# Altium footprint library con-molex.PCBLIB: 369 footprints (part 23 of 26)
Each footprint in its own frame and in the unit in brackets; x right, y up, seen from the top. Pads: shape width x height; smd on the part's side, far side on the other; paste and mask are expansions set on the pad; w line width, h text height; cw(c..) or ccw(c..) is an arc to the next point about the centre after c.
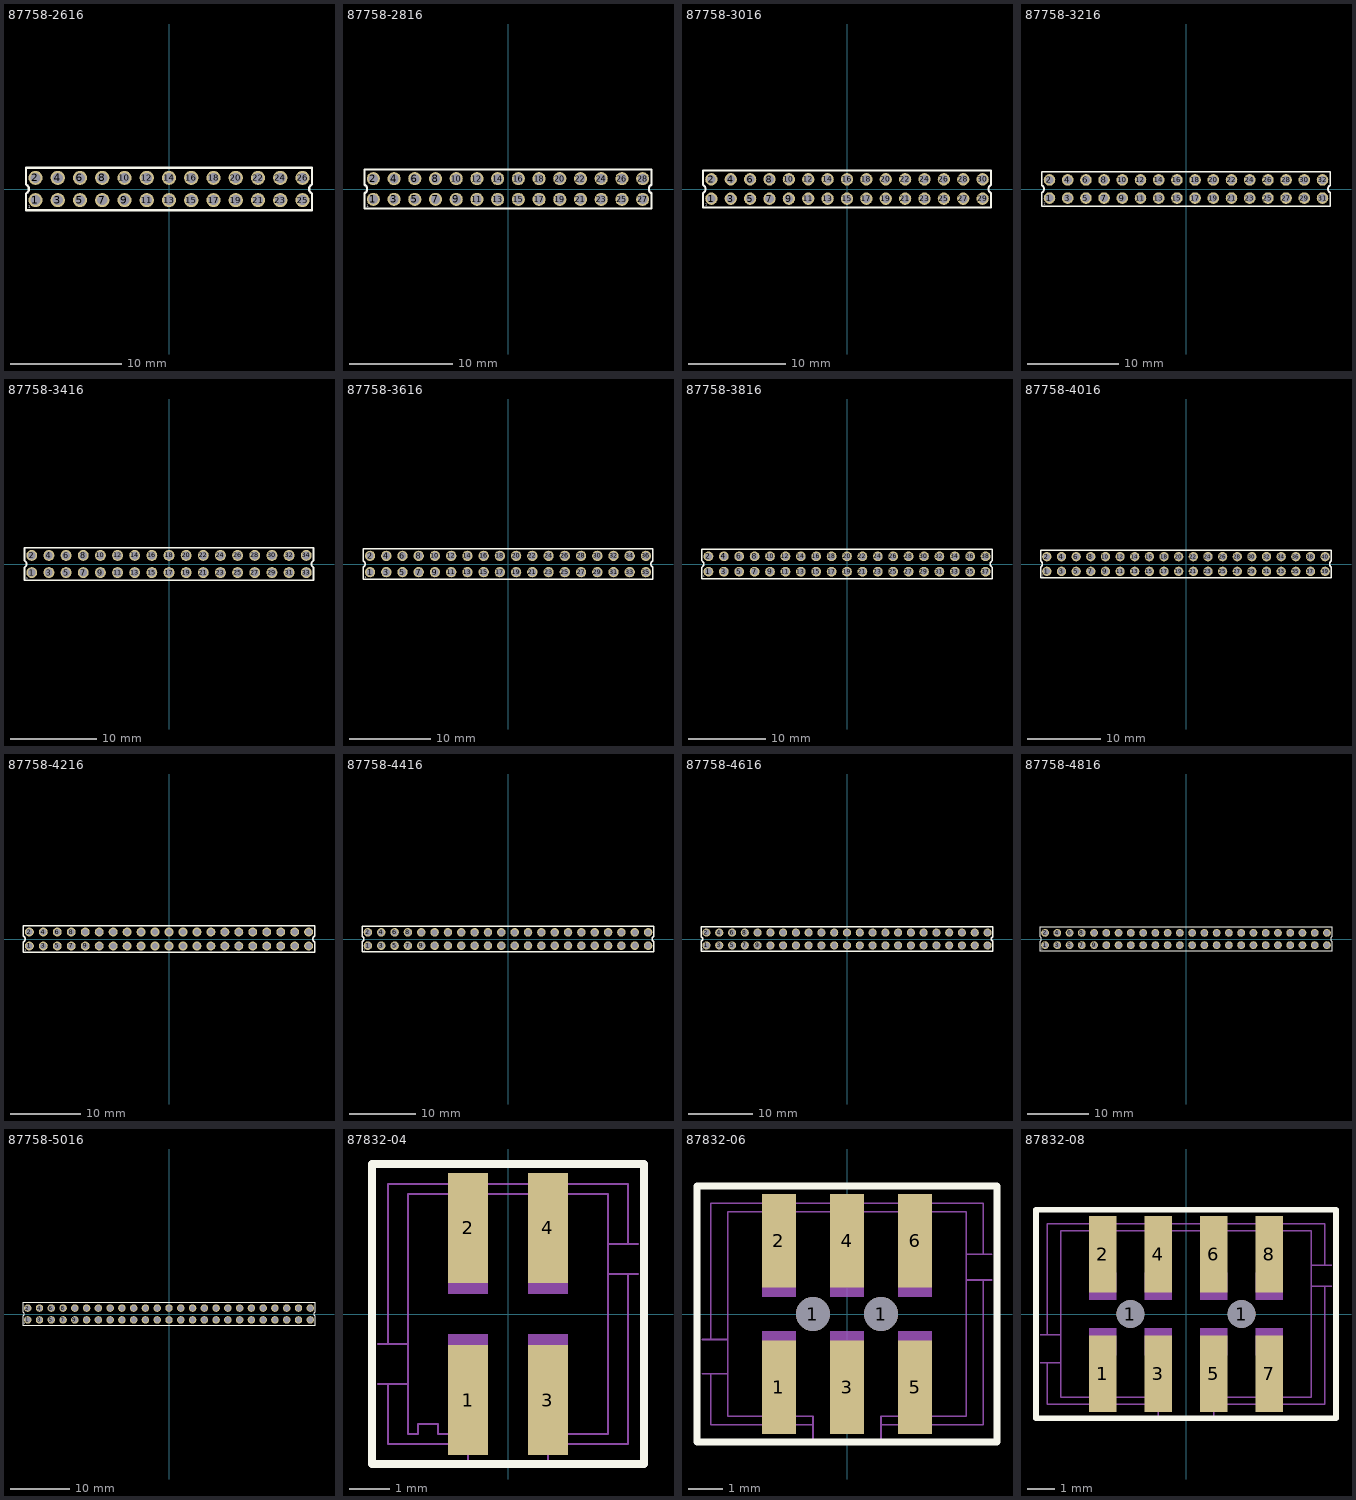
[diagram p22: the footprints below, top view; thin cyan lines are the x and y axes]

## 87758-2616 [mm]
pads (26):
  round 1.27 hole 0.9: 1(-12,-1) 2(-12,1) 3(-10,-1) 4(-10,1) 5(-8,-1) 6(-8,1) 7(-6,-1) 8(-6,1) 9(-4,-1) 10(-4,1) 11(-2,-1) 12(-2,1) 13(0,-1) 14(0,1) 15(2,-1) 16(2,1) 17(4,-1) 18(4,1) 19(6,-1) 20(6,1) 21(8,-1) 22(8,1) 23(10,-1) 24(10,1) 25(12,-1) 26(12,1)
Top Overlay:
  lines w0.203: -12.85,-1.9 12.85,-1.9 12.85,-0.4 cw(c13.04,0) 12.85,0.4 12.85,1.9 -12.85,1.9 -12.85,0.4 cw(c-13.04,0) -12.85,-0.4 -12.85,-1.9
  text "1" at -12.65,-1.75 h0.26
Mechanical 16:
  rectangle: -12.25,-1.25 -11.75,-0.75
  rectangle: -12.25,0.75 -11.75,1.25
  rectangle: -10.25,-1.25 -9.75,-0.75
  rectangle: -10.25,0.75 -9.75,1.25
  rectangle: -8.25,-1.25 -7.75,-0.75
  rectangle: -8.25,0.75 -7.75,1.25
  rectangle: -6.25,-1.25 -5.75,-0.75
  rectangle: -6.25,0.75 -5.75,1.25
  rectangle: -4.25,-1.25 -3.75,-0.75
  rectangle: -4.25,0.75 -3.75,1.25
  rectangle: -2.25,-1.25 -1.75,-0.75
  rectangle: -2.25,0.75 -1.75,1.25
  rectangle: -0.25,-1.25 0.25,-0.75
  rectangle: -0.25,0.75 0.25,1.25
  rectangle: 1.75,-1.25 2.25,-0.75
  rectangle: 1.75,0.75 2.25,1.25
  rectangle: 3.75,-1.25 4.25,-0.75
  rectangle: 3.75,0.75 4.25,1.25
  rectangle: 5.75,-1.25 6.25,-0.75
  rectangle: 5.75,0.75 6.25,1.25
  rectangle: 7.75,-1.25 8.25,-0.75
  rectangle: 7.75,0.75 8.25,1.25
  rectangle: 9.75,-1.25 10.25,-0.75
  rectangle: 9.75,0.75 10.25,1.25
  rectangle: 11.75,-1.25 12.25,-0.75
  rectangle: 11.75,0.75 12.25,1.25

## 87758-2816 [mm]
pads (28):
  round 1.27 hole 0.9: 1(-13,-1) 2(-13,1) 3(-11,-1) 4(-11,1) 5(-9,-1) 6(-9,1) 7(-7,-1) 8(-7,1) 9(-5,-1) 10(-5,1) 11(-3,-1) 12(-3,1) 13(-1,-1) 14(-1,1) 15(1,-1) 16(1,1) 17(3,-1) 18(3,1) 19(5,-1) 20(5,1) 21(7,-1) 22(7,1) 23(9,-1) 24(9,1) 25(11,-1) 26(11,1) 27(13,-1) 28(13,1)
Top Overlay:
  lines w0.203: -13.85,-1.9 13.85,-1.9 13.85,-0.4 cw(c14.04,0) 13.85,0.4 13.85,1.9 -13.85,1.9 -13.85,0.4 cw(c-14.04,0) -13.85,-0.4 -13.85,-1.9
  text "1" at -13.65,-1.75 h0.26
Mechanical 16:
  rectangle: -13.25,-1.25 -12.75,-0.75
  rectangle: -13.25,0.75 -12.75,1.25
  rectangle: -11.25,-1.25 -10.75,-0.75
  rectangle: -11.25,0.75 -10.75,1.25
  rectangle: -9.25,-1.25 -8.75,-0.75
  rectangle: -9.25,0.75 -8.75,1.25
  rectangle: -7.25,-1.25 -6.75,-0.75
  rectangle: -7.25,0.75 -6.75,1.25
  rectangle: -5.25,-1.25 -4.75,-0.75
  rectangle: -5.25,0.75 -4.75,1.25
  rectangle: -3.25,-1.25 -2.75,-0.75
  rectangle: -3.25,0.75 -2.75,1.25
  rectangle: -1.25,-1.25 -0.75,-0.75
  rectangle: -1.25,0.75 -0.75,1.25
  rectangle: 0.75,-1.25 1.25,-0.75
  rectangle: 0.75,0.75 1.25,1.25
  rectangle: 2.75,-1.25 3.25,-0.75
  rectangle: 2.75,0.75 3.25,1.25
  rectangle: 4.75,-1.25 5.25,-0.75
  rectangle: 4.75,0.75 5.25,1.25
  rectangle: 6.75,-1.25 7.25,-0.75
  rectangle: 6.75,0.75 7.25,1.25
  rectangle: 8.75,-1.25 9.25,-0.75
  rectangle: 8.75,0.75 9.25,1.25
  rectangle: 10.75,-1.25 11.25,-0.75
  rectangle: 10.75,0.75 11.25,1.25
  rectangle: 12.75,-1.25 13.25,-0.75
  rectangle: 12.75,0.75 13.25,1.25

## 87758-3016 [mm]
pads (30):
  round 1.27 hole 0.9: 1(-14,-1) 2(-14,1) 3(-12,-1) 4(-12,1) 5(-10,-1) 6(-10,1) 7(-8,-1) 8(-8,1) 9(-6,-1) 10(-6,1) 11(-4,-1) 12(-4,1) 13(-2,-1) 14(-2,1) 15(0,-1) 16(0,1) 17(2,-1) 18(2,1) 19(4,-1) 20(4,1) 21(6,-1) 22(6,1) 23(8,-1) 24(8,1) 25(10,-1) 26(10,1) 27(12,-1) 28(12,1) 29(14,-1) 30(14,1)
Top Overlay:
  lines w0.203: -14.85,-1.9 14.85,-1.9 14.85,-0.4 cw(c15.04,0) 14.85,0.4 14.85,1.9 -14.85,1.9 -14.85,0.4 cw(c-15.04,0) -14.85,-0.4 -14.85,-1.9
  text "1" at -14.65,-1.75 h0.26
Mechanical 16:
  rectangle: -14.25,-1.25 -13.75,-0.75
  rectangle: -14.25,0.75 -13.75,1.25
  rectangle: -12.25,-1.25 -11.75,-0.75
  rectangle: -12.25,0.75 -11.75,1.25
  rectangle: -10.25,-1.25 -9.75,-0.75
  rectangle: -10.25,0.75 -9.75,1.25
  rectangle: -8.25,-1.25 -7.75,-0.75
  rectangle: -8.25,0.75 -7.75,1.25
  rectangle: -6.25,-1.25 -5.75,-0.75
  rectangle: -6.25,0.75 -5.75,1.25
  rectangle: -4.25,-1.25 -3.75,-0.75
  rectangle: -4.25,0.75 -3.75,1.25
  rectangle: -2.25,-1.25 -1.75,-0.75
  rectangle: -2.25,0.75 -1.75,1.25
  rectangle: -0.25,-1.25 0.25,-0.75
  rectangle: -0.25,0.75 0.25,1.25
  rectangle: 1.75,-1.25 2.25,-0.75
  rectangle: 1.75,0.75 2.25,1.25
  rectangle: 3.75,-1.25 4.25,-0.75
  rectangle: 3.75,0.75 4.25,1.25
  rectangle: 5.75,-1.25 6.25,-0.75
  rectangle: 5.75,0.75 6.25,1.25
  rectangle: 7.75,-1.25 8.25,-0.75
  rectangle: 7.75,0.75 8.25,1.25
  rectangle: 9.75,-1.25 10.25,-0.75
  rectangle: 9.75,0.75 10.25,1.25
  rectangle: 11.75,-1.25 12.25,-0.75
  rectangle: 11.75,0.75 12.25,1.25
  rectangle: 13.75,-1.25 14.25,-0.75
  rectangle: 13.75,0.75 14.25,1.25

## 87758-3216 [mm]
pads (32):
  round 1.27 hole 0.9: 1(-15,-1) 2(-15,1) 3(-13,-1) 4(-13,1) 5(-11,-1) 6(-11,1) 7(-9,-1) 8(-9,1) 9(-7,-1) 10(-7,1) 11(-5,-1) 12(-5,1) 13(-3,-1) 14(-3,1) 15(-1,-1) 16(-1,1) 17(1,-1) 18(1,1) 19(3,-1) 20(3,1) 21(5,-1) 22(5,1) 23(7,-1) 24(7,1) 25(9,-1) 26(9,1) 27(11,-1) 28(11,1) 29(13,-1) 30(13,1) 31(15,-1) 32(15,1)
Top Overlay:
  lines w0.203: -15.85,-1.9 15.85,-1.9 15.85,-0.4 cw(c16.04,0) 15.85,0.4 15.85,1.9 -15.85,1.9 -15.85,0.4 cw(c-16.04,0) -15.85,-0.4 -15.85,-1.9
  text "1" at -15.65,-1.75 h0.26
Mechanical 16:
  rectangle: -15.25,-1.25 -14.75,-0.75
  rectangle: -15.25,0.75 -14.75,1.25
  rectangle: -13.25,-1.25 -12.75,-0.75
  rectangle: -13.25,0.75 -12.75,1.25
  rectangle: -11.25,-1.25 -10.75,-0.75
  rectangle: -11.25,0.75 -10.75,1.25
  rectangle: -9.25,-1.25 -8.75,-0.75
  rectangle: -9.25,0.75 -8.75,1.25
  rectangle: -7.25,-1.25 -6.75,-0.75
  rectangle: -7.25,0.75 -6.75,1.25
  rectangle: -5.25,-1.25 -4.75,-0.75
  rectangle: -5.25,0.75 -4.75,1.25
  rectangle: -3.25,-1.25 -2.75,-0.75
  rectangle: -3.25,0.75 -2.75,1.25
  rectangle: -1.25,-1.25 -0.75,-0.75
  rectangle: -1.25,0.75 -0.75,1.25
  rectangle: 0.75,-1.25 1.25,-0.75
  rectangle: 0.75,0.75 1.25,1.25
  rectangle: 2.75,-1.25 3.25,-0.75
  rectangle: 2.75,0.75 3.25,1.25
  rectangle: 4.75,-1.25 5.25,-0.75
  rectangle: 4.75,0.75 5.25,1.25
  rectangle: 6.75,-1.25 7.25,-0.75
  rectangle: 6.75,0.75 7.25,1.25
  rectangle: 8.75,-1.25 9.25,-0.75
  rectangle: 8.75,0.75 9.25,1.25
  rectangle: 10.75,-1.25 11.25,-0.75
  rectangle: 10.75,0.75 11.25,1.25
  rectangle: 12.75,-1.25 13.25,-0.75
  rectangle: 12.75,0.75 13.25,1.25
  rectangle: 14.75,-1.25 15.25,-0.75
  rectangle: 14.75,0.75 15.25,1.25

## 87758-3416 [mm]
pads (34):
  round 1.27 hole 0.9: 1(-16,-1) 2(-16,1) 3(-14,-1) 4(-14,1) 5(-12,-1) 6(-12,1) 7(-10,-1) 8(-10,1) 9(-8,-1) 10(-8,1) 11(-6,-1) 12(-6,1) 13(-4,-1) 14(-4,1) 15(-2,-1) 16(-2,1) 17(0,-1) 18(0,1) 19(2,-1) 20(2,1) 21(4,-1) 22(4,1) 23(6,-1) 24(6,1) 25(8,-1) 26(8,1) 27(10,-1) 28(10,1) 29(12,-1) 30(12,1) 31(14,-1) 32(14,1) 33(16,-1) 34(16,1)
Top Overlay:
  lines w0.203: -16.85,-1.9 16.85,-1.9 16.85,-0.4 cw(c17.04,0) 16.85,0.4 16.85,1.9 -16.85,1.9 -16.85,0.4 cw(c-17.04,0) -16.85,-0.4 -16.85,-1.9
  text "1" at -16.65,-1.75 h0.26
Mechanical 16:
  rectangle: -16.25,-1.25 -15.75,-0.75
  rectangle: -16.25,0.75 -15.75,1.25
  rectangle: -14.25,-1.25 -13.75,-0.75
  rectangle: -14.25,0.75 -13.75,1.25
  rectangle: -12.25,-1.25 -11.75,-0.75
  rectangle: -12.25,0.75 -11.75,1.25
  rectangle: -10.25,-1.25 -9.75,-0.75
  rectangle: -10.25,0.75 -9.75,1.25
  rectangle: -8.25,-1.25 -7.75,-0.75
  rectangle: -8.25,0.75 -7.75,1.25
  rectangle: -6.25,-1.25 -5.75,-0.75
  rectangle: -6.25,0.75 -5.75,1.25
  rectangle: -4.25,-1.25 -3.75,-0.75
  rectangle: -4.25,0.75 -3.75,1.25
  rectangle: -2.25,-1.25 -1.75,-0.75
  rectangle: -2.25,0.75 -1.75,1.25
  rectangle: -0.25,-1.25 0.25,-0.75
  rectangle: -0.25,0.75 0.25,1.25
  rectangle: 1.75,-1.25 2.25,-0.75
  rectangle: 1.75,0.75 2.25,1.25
  rectangle: 3.75,-1.25 4.25,-0.75
  rectangle: 3.75,0.75 4.25,1.25
  rectangle: 5.75,-1.25 6.25,-0.75
  rectangle: 5.75,0.75 6.25,1.25
  rectangle: 7.75,-1.25 8.25,-0.75
  rectangle: 7.75,0.75 8.25,1.25
  rectangle: 9.75,-1.25 10.25,-0.75
  rectangle: 9.75,0.75 10.25,1.25
  rectangle: 11.75,-1.25 12.25,-0.75
  rectangle: 11.75,0.75 12.25,1.25
  rectangle: 13.75,-1.25 14.25,-0.75
  rectangle: 13.75,0.75 14.25,1.25
  rectangle: 15.75,-1.25 16.25,-0.75
  rectangle: 15.75,0.75 16.25,1.25

## 87758-3616 [mm]
pads (36):
  round 1.27 hole 0.9: 1(-17,-1) 2(-17,1) 3(-15,-1) 4(-15,1) 5(-13,-1) 6(-13,1) 7(-11,-1) 8(-11,1) 9(-9,-1) 10(-9,1) 11(-7,-1) 12(-7,1) 13(-5,-1) 14(-5,1) 15(-3,-1) 16(-3,1) 17(-1,-1) 18(-1,1) 19(1,-1) 20(1,1) 21(3,-1) 22(3,1) 23(5,-1) 24(5,1) 25(7,-1) 26(7,1) 27(9,-1) 28(9,1) 29(11,-1) 30(11,1) 31(13,-1) 32(13,1) 33(15,-1) 34(15,1) 35(17,-1) 36(17,1)
Top Overlay:
  lines w0.203: -17.85,-1.9 17.85,-1.9 17.85,-0.4 cw(c18.04,0) 17.85,0.4 17.85,1.9 -17.85,1.9 -17.85,0.4 cw(c-18.04,0) -17.85,-0.4 -17.85,-1.9
  text "1" at -17.65,-1.75 h0.26
Mechanical 16:
  rectangle: -17.25,-1.25 -16.75,-0.75
  rectangle: -17.25,0.75 -16.75,1.25
  rectangle: -15.25,-1.25 -14.75,-0.75
  rectangle: -15.25,0.75 -14.75,1.25
  rectangle: -13.25,-1.25 -12.75,-0.75
  rectangle: -13.25,0.75 -12.75,1.25
  rectangle: -11.25,-1.25 -10.75,-0.75
  rectangle: -11.25,0.75 -10.75,1.25
  rectangle: -9.25,-1.25 -8.75,-0.75
  rectangle: -9.25,0.75 -8.75,1.25
  rectangle: -7.25,-1.25 -6.75,-0.75
  rectangle: -7.25,0.75 -6.75,1.25
  rectangle: -5.25,-1.25 -4.75,-0.75
  rectangle: -5.25,0.75 -4.75,1.25
  rectangle: -3.25,-1.25 -2.75,-0.75
  rectangle: -3.25,0.75 -2.75,1.25
  rectangle: -1.25,-1.25 -0.75,-0.75
  rectangle: -1.25,0.75 -0.75,1.25
  rectangle: 0.75,-1.25 1.25,-0.75
  rectangle: 0.75,0.75 1.25,1.25
  rectangle: 2.75,-1.25 3.25,-0.75
  rectangle: 2.75,0.75 3.25,1.25
  rectangle: 4.75,-1.25 5.25,-0.75
  rectangle: 4.75,0.75 5.25,1.25
  rectangle: 6.75,-1.25 7.25,-0.75
  rectangle: 6.75,0.75 7.25,1.25
  rectangle: 8.75,-1.25 9.25,-0.75
  rectangle: 8.75,0.75 9.25,1.25
  rectangle: 10.75,-1.25 11.25,-0.75
  rectangle: 10.75,0.75 11.25,1.25
  rectangle: 12.75,-1.25 13.25,-0.75
  rectangle: 12.75,0.75 13.25,1.25
  rectangle: 14.75,-1.25 15.25,-0.75
  rectangle: 14.75,0.75 15.25,1.25
  rectangle: 16.75,-1.25 17.25,-0.75
  rectangle: 16.75,0.75 17.25,1.25

## 87758-3816 [mm]
pads (38):
  round 1.27 hole 0.9: 1(-18,-1) 2(-18,1) 3(-16,-1) 4(-16,1) 5(-14,-1) 6(-14,1) 7(-12,-1) 8(-12,1) 9(-10,-1) 10(-10,1) 11(-8,-1) 12(-8,1) 13(-6,-1) 14(-6,1) 15(-4,-1) 16(-4,1) 17(-2,-1) 18(-2,1) 19(0,-1) 20(0,1) 21(2,-1) 22(2,1) 23(4,-1) 24(4,1) 25(6,-1) 26(6,1) 27(8,-1) 28(8,1) 29(10,-1) 30(10,1) 31(12,-1) 32(12,1) 33(14,-1) 34(14,1) 35(16,-1) 36(16,1) 37(18,-1) 38(18,1)
Top Overlay:
  lines w0.203: -18.85,-1.9 18.85,-1.9 18.85,-0.4 cw(c19.04,0) 18.85,0.4 18.85,1.9 -18.85,1.9 -18.85,0.4 cw(c-19.04,0) -18.85,-0.4 -18.85,-1.9
  text "1" at -18.65,-1.75 h0.26
Mechanical 16:
  rectangle: -18.25,-1.25 -17.75,-0.75
  rectangle: -18.25,0.75 -17.75,1.25
  rectangle: -16.25,-1.25 -15.75,-0.75
  rectangle: -16.25,0.75 -15.75,1.25
  rectangle: -14.25,-1.25 -13.75,-0.75
  rectangle: -14.25,0.75 -13.75,1.25
  rectangle: -12.25,-1.25 -11.75,-0.75
  rectangle: -12.25,0.75 -11.75,1.25
  rectangle: -10.25,-1.25 -9.75,-0.75
  rectangle: -10.25,0.75 -9.75,1.25
  rectangle: -8.25,-1.25 -7.75,-0.75
  rectangle: -8.25,0.75 -7.75,1.25
  rectangle: -6.25,-1.25 -5.75,-0.75
  rectangle: -6.25,0.75 -5.75,1.25
  rectangle: -4.25,-1.25 -3.75,-0.75
  rectangle: -4.25,0.75 -3.75,1.25
  rectangle: -2.25,-1.25 -1.75,-0.75
  rectangle: -2.25,0.75 -1.75,1.25
  rectangle: -0.25,-1.25 0.25,-0.75
  rectangle: -0.25,0.75 0.25,1.25
  rectangle: 1.75,-1.25 2.25,-0.75
  rectangle: 1.75,0.75 2.25,1.25
  rectangle: 3.75,-1.25 4.25,-0.75
  rectangle: 3.75,0.75 4.25,1.25
  rectangle: 5.75,-1.25 6.25,-0.75
  rectangle: 5.75,0.75 6.25,1.25
  rectangle: 7.75,-1.25 8.25,-0.75
  rectangle: 7.75,0.75 8.25,1.25
  rectangle: 9.75,-1.25 10.25,-0.75
  rectangle: 9.75,0.75 10.25,1.25
  rectangle: 11.75,-1.25 12.25,-0.75
  rectangle: 11.75,0.75 12.25,1.25
  rectangle: 13.75,-1.25 14.25,-0.75
  rectangle: 13.75,0.75 14.25,1.25
  rectangle: 15.75,-1.25 16.25,-0.75
  rectangle: 15.75,0.75 16.25,1.25
  rectangle: 17.75,-1.25 18.25,-0.75
  rectangle: 17.75,0.75 18.25,1.25

## 87758-4016 [mm]
pads (40):
  round 1.27 hole 0.9: 1(-19,-1) 2(-19,1) 3(-17,-1) 4(-17,1) 5(-15,-1) 6(-15,1) 7(-13,-1) 8(-13,1) 9(-11,-1) 10(-11,1) 11(-9,-1) 12(-9,1) 13(-7,-1) 14(-7,1) 15(-5,-1) 16(-5,1) 17(-3,-1) 18(-3,1) 19(-1,-1) 20(-1,1) 21(1,-1) 22(1,1) 23(3,-1) 24(3,1) 25(5,-1) 26(5,1) 27(7,-1) 28(7,1) 29(9,-1) 30(9,1) 31(11,-1) 32(11,1) 33(13,-1) 34(13,1) 35(15,-1) 36(15,1) 37(17,-1) 38(17,1) 39(19,-1) 40(19,1)
Top Overlay:
  lines w0.203: -19.85,-1.9 19.85,-1.9 19.85,-0.4 cw(c20.04,0) 19.85,0.4 19.85,1.9 -19.85,1.9 -19.85,0.4 cw(c-20.04,0) -19.85,-0.4 -19.85,-1.9
  text "1" at -19.65,-1.75 h0.26
Mechanical 16:
  rectangle: -19.25,-1.25 -18.75,-0.75
  rectangle: -19.25,0.75 -18.75,1.25
  rectangle: -17.25,-1.25 -16.75,-0.75
  rectangle: -17.25,0.75 -16.75,1.25
  rectangle: -15.25,-1.25 -14.75,-0.75
  rectangle: -15.25,0.75 -14.75,1.25
  rectangle: -13.25,-1.25 -12.75,-0.75
  rectangle: -13.25,0.75 -12.75,1.25
  rectangle: -11.25,-1.25 -10.75,-0.75
  rectangle: -11.25,0.75 -10.75,1.25
  rectangle: -9.25,-1.25 -8.75,-0.75
  rectangle: -9.25,0.75 -8.75,1.25
  rectangle: -7.25,-1.25 -6.75,-0.75
  rectangle: -7.25,0.75 -6.75,1.25
  rectangle: -5.25,-1.25 -4.75,-0.75
  rectangle: -5.25,0.75 -4.75,1.25
  rectangle: -3.25,-1.25 -2.75,-0.75
  rectangle: -3.25,0.75 -2.75,1.25
  rectangle: -1.25,-1.25 -0.75,-0.75
  rectangle: -1.25,0.75 -0.75,1.25
  rectangle: 0.75,-1.25 1.25,-0.75
  rectangle: 0.75,0.75 1.25,1.25
  rectangle: 2.75,-1.25 3.25,-0.75
  rectangle: 2.75,0.75 3.25,1.25
  rectangle: 4.75,-1.25 5.25,-0.75
  rectangle: 4.75,0.75 5.25,1.25
  rectangle: 6.75,-1.25 7.25,-0.75
  rectangle: 6.75,0.75 7.25,1.25
  rectangle: 8.75,-1.25 9.25,-0.75
  rectangle: 8.75,0.75 9.25,1.25
  rectangle: 10.75,-1.25 11.25,-0.75
  rectangle: 10.75,0.75 11.25,1.25
  rectangle: 12.75,-1.25 13.25,-0.75
  rectangle: 12.75,0.75 13.25,1.25
  rectangle: 14.75,-1.25 15.25,-0.75
  rectangle: 14.75,0.75 15.25,1.25
  rectangle: 16.75,-1.25 17.25,-0.75
  rectangle: 16.75,0.75 17.25,1.25
  rectangle: 18.75,-1.25 19.25,-0.75
  rectangle: 18.75,0.75 19.25,1.25

## 87758-4216 [mm]
pads (42):
  round 1.27 hole 0.9: 1(-20,-1) 2(-20,1) 3(-18,-1) 4(-18,1) 5(-16,-1) 6(-16,1) 7(-14,-1) 8(-14,1) 9(-12,-1) 10(-12,1) 11(-10,-1) 12(-10,1) 13(-8,-1) 14(-8,1) 15(-6,-1) 16(-6,1) 17(-4,-1) 18(-4,1) 19(-2,-1) 20(-2,1) 21(0,-1) 22(0,1) 23(2,-1) 24(2,1) 25(4,-1) 26(4,1) 27(6,-1) 28(6,1) 29(8,-1) 30(8,1) 31(10,-1) 32(10,1) 33(12,-1) 34(12,1) 35(14,-1) 36(14,1) 37(16,-1) 38(16,1) 39(18,-1) 40(18,1) 41(20,-1) 42(20,1)
Top Overlay:
  lines w0.203: -20.85,-1.9 20.85,-1.9 20.85,-0.4 cw(c21.04,0) 20.85,0.4 20.85,1.9 -20.85,1.9 -20.85,0.4 cw(c-21.04,0) -20.85,-0.4 -20.85,-1.9
  text "1" at -20.65,-1.75 h0.26
Mechanical 16:
  rectangle: -20.25,-1.25 -19.75,-0.75
  rectangle: -20.25,0.75 -19.75,1.25
  rectangle: -18.25,-1.25 -17.75,-0.75
  rectangle: -18.25,0.75 -17.75,1.25
  rectangle: -16.25,-1.25 -15.75,-0.75
  rectangle: -16.25,0.75 -15.75,1.25
  rectangle: -14.25,-1.25 -13.75,-0.75
  rectangle: -14.25,0.75 -13.75,1.25
  rectangle: -12.25,-1.25 -11.75,-0.75
  rectangle: -12.25,0.75 -11.75,1.25
  rectangle: -10.25,-1.25 -9.75,-0.75
  rectangle: -10.25,0.75 -9.75,1.25
  rectangle: -8.25,-1.25 -7.75,-0.75
  rectangle: -8.25,0.75 -7.75,1.25
  rectangle: -6.25,-1.25 -5.75,-0.75
  rectangle: -6.25,0.75 -5.75,1.25
  rectangle: -4.25,-1.25 -3.75,-0.75
  rectangle: -4.25,0.75 -3.75,1.25
  rectangle: -2.25,-1.25 -1.75,-0.75
  rectangle: -2.25,0.75 -1.75,1.25
  rectangle: -0.25,-1.25 0.25,-0.75
  rectangle: -0.25,0.75 0.25,1.25
  rectangle: 1.75,-1.25 2.25,-0.75
  rectangle: 1.75,0.75 2.25,1.25
  rectangle: 3.75,-1.25 4.25,-0.75
  rectangle: 3.75,0.75 4.25,1.25
  rectangle: 5.75,-1.25 6.25,-0.75
  rectangle: 5.75,0.75 6.25,1.25
  rectangle: 7.75,-1.25 8.25,-0.75
  rectangle: 7.75,0.75 8.25,1.25
  rectangle: 9.75,-1.25 10.25,-0.75
  rectangle: 9.75,0.75 10.25,1.25
  rectangle: 11.75,-1.25 12.25,-0.75
  rectangle: 11.75,0.75 12.25,1.25
  rectangle: 13.75,-1.25 14.25,-0.75
  rectangle: 13.75,0.75 14.25,1.25
  rectangle: 15.75,-1.25 16.25,-0.75
  rectangle: 15.75,0.75 16.25,1.25
  rectangle: 17.75,-1.25 18.25,-0.75
  rectangle: 17.75,0.75 18.25,1.25
  rectangle: 19.75,-1.25 20.25,-0.75
  rectangle: 19.75,0.75 20.25,1.25

## 87758-4416 [mm]
pads (44):
  round 1.27 hole 0.9: 1(-21,-1) 2(-21,1) 3(-19,-1) 4(-19,1) 5(-17,-1) 6(-17,1) 7(-15,-1) 8(-15,1) 9(-13,-1) 10(-13,1) 11(-11,-1) 12(-11,1) 13(-9,-1) 14(-9,1) 15(-7,-1) 16(-7,1) 17(-5,-1) 18(-5,1) 19(-3,-1) 20(-3,1) 21(-1,-1) 22(-1,1) 23(1,-1) 24(1,1) 25(3,-1) 26(3,1) 27(5,-1) 28(5,1) 29(7,-1) 30(7,1) 31(9,-1) 32(9,1) 33(11,-1) 34(11,1) 35(13,-1) 36(13,1) 37(15,-1) 38(15,1) 39(17,-1) 40(17,1) 41(19,-1) 42(19,1) 43(21,-1) 44(21,1)
Top Overlay:
  lines w0.203: -21.85,-1.9 21.85,-1.9 21.85,-0.4 cw(c22.04,0) 21.85,0.4 21.85,1.9 -21.85,1.9 -21.85,0.4 cw(c-22.04,0) -21.85,-0.4 -21.85,-1.9
  text "1" at -21.65,-1.75 h0.26
Mechanical 16:
  rectangle: -21.25,-1.25 -20.75,-0.75
  rectangle: -21.25,0.75 -20.75,1.25
  rectangle: -19.25,-1.25 -18.75,-0.75
  rectangle: -19.25,0.75 -18.75,1.25
  rectangle: -17.25,-1.25 -16.75,-0.75
  rectangle: -17.25,0.75 -16.75,1.25
  rectangle: -15.25,-1.25 -14.75,-0.75
  rectangle: -15.25,0.75 -14.75,1.25
  rectangle: -13.25,-1.25 -12.75,-0.75
  rectangle: -13.25,0.75 -12.75,1.25
  rectangle: -11.25,-1.25 -10.75,-0.75
  rectangle: -11.25,0.75 -10.75,1.25
  rectangle: -9.25,-1.25 -8.75,-0.75
  rectangle: -9.25,0.75 -8.75,1.25
  rectangle: -7.25,-1.25 -6.75,-0.75
  rectangle: -7.25,0.75 -6.75,1.25
  rectangle: -5.25,-1.25 -4.75,-0.75
  rectangle: -5.25,0.75 -4.75,1.25
  rectangle: -3.25,-1.25 -2.75,-0.75
  rectangle: -3.25,0.75 -2.75,1.25
  rectangle: -1.25,-1.25 -0.75,-0.75
  rectangle: -1.25,0.75 -0.75,1.25
  rectangle: 0.75,-1.25 1.25,-0.75
  rectangle: 0.75,0.75 1.25,1.25
  rectangle: 2.75,-1.25 3.25,-0.75
  rectangle: 2.75,0.75 3.25,1.25
  rectangle: 4.75,-1.25 5.25,-0.75
  rectangle: 4.75,0.75 5.25,1.25
  rectangle: 6.75,-1.25 7.25,-0.75
  rectangle: 6.75,0.75 7.25,1.25
  rectangle: 8.75,-1.25 9.25,-0.75
  rectangle: 8.75,0.75 9.25,1.25
  rectangle: 10.75,-1.25 11.25,-0.75
  rectangle: 10.75,0.75 11.25,1.25
  rectangle: 12.75,-1.25 13.25,-0.75
  rectangle: 12.75,0.75 13.25,1.25
  rectangle: 14.75,-1.25 15.25,-0.75
  rectangle: 14.75,0.75 15.25,1.25
  rectangle: 16.75,-1.25 17.25,-0.75
  rectangle: 16.75,0.75 17.25,1.25
  rectangle: 18.75,-1.25 19.25,-0.75
  rectangle: 18.75,0.75 19.25,1.25
  rectangle: 20.75,-1.25 21.25,-0.75
  rectangle: 20.75,0.75 21.25,1.25

## 87758-4616 [mm]
pads (46):
  round 1.27 hole 0.9: 1(-22,-1) 2(-22,1) 3(-20,-1) 4(-20,1) 5(-18,-1) 6(-18,1) 7(-16,-1) 8(-16,1) 9(-14,-1) 10(-14,1) 11(-12,-1) 12(-12,1) 13(-10,-1) 14(-10,1) 15(-8,-1) 16(-8,1) 17(-6,-1) 18(-6,1) 19(-4,-1) 20(-4,1) 21(-2,-1) 22(-2,1) 23(0,-1) 24(0,1) 25(2,-1) 26(2,1) 27(4,-1) 28(4,1) 29(6,-1) 30(6,1) 31(8,-1) 32(8,1) 33(10,-1) 34(10,1) 35(12,-1) 36(12,1) 37(14,-1) 38(14,1) 39(16,-1) 40(16,1) 41(18,-1) 42(18,1) 43(20,-1) 44(20,1) 45(22,-1) 46(22,1)
Top Overlay:
  lines w0.203: -22.85,-1.9 22.85,-1.9 22.85,-0.4 cw(c23.04,0) 22.85,0.4 22.85,1.9 -22.85,1.9 -22.85,0.4 cw(c-23.04,0) -22.85,-0.4 -22.85,-1.9
  text "1" at -22.65,-1.75 h0.26
Mechanical 16:
  rectangle: -22.25,-1.25 -21.75,-0.75
  rectangle: -22.25,0.75 -21.75,1.25
  rectangle: -20.25,-1.25 -19.75,-0.75
  rectangle: -20.25,0.75 -19.75,1.25
  rectangle: -18.25,-1.25 -17.75,-0.75
  rectangle: -18.25,0.75 -17.75,1.25
  rectangle: -16.25,-1.25 -15.75,-0.75
  rectangle: -16.25,0.75 -15.75,1.25
  rectangle: -14.25,-1.25 -13.75,-0.75
  rectangle: -14.25,0.75 -13.75,1.25
  rectangle: -12.25,-1.25 -11.75,-0.75
  rectangle: -12.25,0.75 -11.75,1.25
  rectangle: -10.25,-1.25 -9.75,-0.75
  rectangle: -10.25,0.75 -9.75,1.25
  rectangle: -8.25,-1.25 -7.75,-0.75
  rectangle: -8.25,0.75 -7.75,1.25
  rectangle: -6.25,-1.25 -5.75,-0.75
  rectangle: -6.25,0.75 -5.75,1.25
  rectangle: -4.25,-1.25 -3.75,-0.75
  rectangle: -4.25,0.75 -3.75,1.25
  rectangle: -2.25,-1.25 -1.75,-0.75
  rectangle: -2.25,0.75 -1.75,1.25
  rectangle: -0.25,-1.25 0.25,-0.75
  rectangle: -0.25,0.75 0.25,1.25
  rectangle: 1.75,-1.25 2.25,-0.75
  rectangle: 1.75,0.75 2.25,1.25
  rectangle: 3.75,-1.25 4.25,-0.75
  rectangle: 3.75,0.75 4.25,1.25
  rectangle: 5.75,-1.25 6.25,-0.75
  rectangle: 5.75,0.75 6.25,1.25
  rectangle: 7.75,-1.25 8.25,-0.75
  rectangle: 7.75,0.75 8.25,1.25
  rectangle: 9.75,-1.25 10.25,-0.75
  rectangle: 9.75,0.75 10.25,1.25
  rectangle: 11.75,-1.25 12.25,-0.75
  rectangle: 11.75,0.75 12.25,1.25
  rectangle: 13.75,-1.25 14.25,-0.75
  rectangle: 13.75,0.75 14.25,1.25
  rectangle: 15.75,-1.25 16.25,-0.75
  rectangle: 15.75,0.75 16.25,1.25
  rectangle: 17.75,-1.25 18.25,-0.75
  rectangle: 17.75,0.75 18.25,1.25
  rectangle: 19.75,-1.25 20.25,-0.75
  rectangle: 19.75,0.75 20.25,1.25
  rectangle: 21.75,-1.25 22.25,-0.75
  rectangle: 21.75,0.75 22.25,1.25

## 87758-4816 [mm]
pads (48):
  round 1.27 hole 0.9: 1(-23,-1) 2(-23,1) 3(-21,-1) 4(-21,1) 5(-19,-1) 6(-19,1) 7(-17,-1) 8(-17,1) 9(-15,-1) 10(-15,1) 11(-13,-1) 12(-13,1) 13(-11,-1) 14(-11,1) 15(-9,-1) 16(-9,1) 17(-7,-1) 18(-7,1) 19(-5,-1) 20(-5,1) 21(-3,-1) 22(-3,1) 23(-1,-1) 24(-1,1) 25(1,-1) 26(1,1) 27(3,-1) 28(3,1) 29(5,-1) 30(5,1) 31(7,-1) 32(7,1) 33(9,-1) 34(9,1) 35(11,-1) 36(11,1) 37(13,-1) 38(13,1) 39(15,-1) 40(15,1) 41(17,-1) 42(17,1) 43(19,-1) 44(19,1) 45(21,-1) 46(21,1) 47(23,-1) 48(23,1)
Top Overlay:
  lines w0.203: -23.85,-1.9 23.85,-1.9 23.85,-0.4 cw(c24.04,0) 23.85,0.4 23.85,1.9 -23.85,1.9 -23.85,0.4 cw(c-24.04,0) -23.85,-0.4 -23.85,-1.9
  text "1" at -23.65,-1.75 h0.26
Mechanical 16:
  rectangle: -23.25,-1.25 -22.75,-0.75
  rectangle: -23.25,0.75 -22.75,1.25
  rectangle: -21.25,-1.25 -20.75,-0.75
  rectangle: -21.25,0.75 -20.75,1.25
  rectangle: -19.25,-1.25 -18.75,-0.75
  rectangle: -19.25,0.75 -18.75,1.25
  rectangle: -17.25,-1.25 -16.75,-0.75
  rectangle: -17.25,0.75 -16.75,1.25
  rectangle: -15.25,-1.25 -14.75,-0.75
  rectangle: -15.25,0.75 -14.75,1.25
  rectangle: -13.25,-1.25 -12.75,-0.75
  rectangle: -13.25,0.75 -12.75,1.25
  rectangle: -11.25,-1.25 -10.75,-0.75
  rectangle: -11.25,0.75 -10.75,1.25
  rectangle: -9.25,-1.25 -8.75,-0.75
  rectangle: -9.25,0.75 -8.75,1.25
  rectangle: -7.25,-1.25 -6.75,-0.75
  rectangle: -7.25,0.75 -6.75,1.25
  rectangle: -5.25,-1.25 -4.75,-0.75
  rectangle: -5.25,0.75 -4.75,1.25
  rectangle: -3.25,-1.25 -2.75,-0.75
  rectangle: -3.25,0.75 -2.75,1.25
  rectangle: -1.25,-1.25 -0.75,-0.75
  rectangle: -1.25,0.75 -0.75,1.25
  rectangle: 0.75,-1.25 1.25,-0.75
  rectangle: 0.75,0.75 1.25,1.25
  rectangle: 2.75,-1.25 3.25,-0.75
  rectangle: 2.75,0.75 3.25,1.25
  rectangle: 4.75,-1.25 5.25,-0.75
  rectangle: 4.75,0.75 5.25,1.25
  rectangle: 6.75,-1.25 7.25,-0.75
  rectangle: 6.75,0.75 7.25,1.25
  rectangle: 8.75,-1.25 9.25,-0.75
  rectangle: 8.75,0.75 9.25,1.25
  rectangle: 10.75,-1.25 11.25,-0.75
  rectangle: 10.75,0.75 11.25,1.25
  rectangle: 12.75,-1.25 13.25,-0.75
  rectangle: 12.75,0.75 13.25,1.25
  rectangle: 14.75,-1.25 15.25,-0.75
  rectangle: 14.75,0.75 15.25,1.25
  rectangle: 16.75,-1.25 17.25,-0.75
  rectangle: 16.75,0.75 17.25,1.25
  rectangle: 18.75,-1.25 19.25,-0.75
  rectangle: 18.75,0.75 19.25,1.25
  rectangle: 20.75,-1.25 21.25,-0.75
  rectangle: 20.75,0.75 21.25,1.25
  rectangle: 22.75,-1.25 23.25,-0.75
  rectangle: 22.75,0.75 23.25,1.25

## 87758-5016 [mm]
pads (50):
  round 1.27 hole 0.9: 1(-24,-1) 2(-24,1) 3(-22,-1) 4(-22,1) 5(-20,-1) 6(-20,1) 7(-18,-1) 8(-18,1) 9(-16,-1) 10(-16,1) 11(-14,-1) 12(-14,1) 13(-12,-1) 14(-12,1) 15(-10,-1) 16(-10,1) 17(-8,-1) 18(-8,1) 19(-6,-1) 20(-6,1) 21(-4,-1) 22(-4,1) 23(-2,-1) 24(-2,1) 25(0,-1) 26(0,1) 27(2,-1) 28(2,1) 29(4,-1) 30(4,1) 31(6,-1) 32(6,1) 33(8,-1) 34(8,1) 35(10,-1) 36(10,1) 37(12,-1) 38(12,1) 39(14,-1) 40(14,1) 41(16,-1) 42(16,1) 43(18,-1) 44(18,1) 45(20,-1) 46(20,1) 47(22,-1) 48(22,1) 49(24,-1) 50(24,1)
Top Overlay:
  lines w0.203: -24.85,-1.9 24.85,-1.9 24.85,-0.4 cw(c25.04,0) 24.85,0.4 24.85,1.9 -24.85,1.9 -24.85,0.4 cw(c-25.04,0) -24.85,-0.4 -24.85,-1.9
  text "1" at -24.65,-1.75 h0.26
Mechanical 16:
  rectangle: -24.25,-1.25 -23.75,-0.75
  rectangle: -24.25,0.75 -23.75,1.25
  rectangle: -22.25,-1.25 -21.75,-0.75
  rectangle: -22.25,0.75 -21.75,1.25
  rectangle: -20.25,-1.25 -19.75,-0.75
  rectangle: -20.25,0.75 -19.75,1.25
  rectangle: -18.25,-1.25 -17.75,-0.75
  rectangle: -18.25,0.75 -17.75,1.25
  rectangle: -16.25,-1.25 -15.75,-0.75
  rectangle: -16.25,0.75 -15.75,1.25
  rectangle: -14.25,-1.25 -13.75,-0.75
  rectangle: -14.25,0.75 -13.75,1.25
  rectangle: -12.25,-1.25 -11.75,-0.75
  rectangle: -12.25,0.75 -11.75,1.25
  rectangle: -10.25,-1.25 -9.75,-0.75
  rectangle: -10.25,0.75 -9.75,1.25
  rectangle: -8.25,-1.25 -7.75,-0.75
  rectangle: -8.25,0.75 -7.75,1.25
  rectangle: -6.25,-1.25 -5.75,-0.75
  rectangle: -6.25,0.75 -5.75,1.25
  rectangle: -4.25,-1.25 -3.75,-0.75
  rectangle: -4.25,0.75 -3.75,1.25
  rectangle: -2.25,-1.25 -1.75,-0.75
  rectangle: -2.25,0.75 -1.75,1.25
  rectangle: -0.25,-1.25 0.25,-0.75
  rectangle: -0.25,0.75 0.25,1.25
  rectangle: 1.75,-1.25 2.25,-0.75
  rectangle: 1.75,0.75 2.25,1.25
  rectangle: 3.75,-1.25 4.25,-0.75
  rectangle: 3.75,0.75 4.25,1.25
  rectangle: 5.75,-1.25 6.25,-0.75
  rectangle: 5.75,0.75 6.25,1.25
  rectangle: 7.75,-1.25 8.25,-0.75
  rectangle: 7.75,0.75 8.25,1.25
  rectangle: 9.75,-1.25 10.25,-0.75
  rectangle: 9.75,0.75 10.25,1.25
  rectangle: 11.75,-1.25 12.25,-0.75
  rectangle: 11.75,0.75 12.25,1.25
  rectangle: 13.75,-1.25 14.25,-0.75
  rectangle: 13.75,0.75 14.25,1.25
  rectangle: 15.75,-1.25 16.25,-0.75
  rectangle: 15.75,0.75 16.25,1.25
  rectangle: 17.75,-1.25 18.25,-0.75
  rectangle: 17.75,0.75 18.25,1.25
  rectangle: 19.75,-1.25 20.25,-0.75
  rectangle: 19.75,0.75 20.25,1.25
  rectangle: 21.75,-1.25 22.25,-0.75
  rectangle: 21.75,0.75 22.25,1.25
  rectangle: 23.75,-1.25 24.25,-0.75
  rectangle: 23.75,0.75 24.25,1.25

## 87832-04 [mm]
pads (4):
  rect 1x2.75 smd: 1(-1,-2.15) 2(-1,2.15) 3(1,-2.15) 4(1,2.15)
Top Overlay:
  lines w0.203: -3.4,-3.75 3.4,-3.75 3.4,3.75 -3.4,3.75 -3.4,-3.75
Mechanical 16:
  rectangle: -1.5,0.5 -0.5,1.5
  rectangle: 0.5,0.5 1.5,1.5
  rectangle: -1.5,-1.5 -0.5,-0.5
  rectangle: 0.5,-1.5 1.5,-0.5
  lines w0.051: -3.25,-1.75 -3,-1.75 ; -3.25,-0.75 -3,-0.75 ; -1,-3.75 -1,-3.25 ; 1,-3.75 1,-3.25 ; 3.25,1 3,1 ; 3.25,1.75 3,1.75 ; -3,-1.75 -2.5,-1.75 ; -3,-1.75 -3,-3.25 -1,-3.25 ; -3,-0.75 -2.5,-0.75 ; -3,-0.75 -3,3.25 3,3.25 3,1.75 ; -2.5,-1.75 -2.5,-0.75 ; -2.5,-1.75 -2.5,-3 -2.25,-3 -2.25,-2.75 -1.75,-2.75 -1.75,-3 -1,-3 -1,-3.25 ; -2.5,-0.75 -2.5,3 -1.25,3 -1.25,2.75 -0.75,2.75 -0.75,3 0.75,3 0.75,2.75 1.25,2.75 1.25,3 2.5,3 2.5,1.75 ; 1,-3.25 1,-3 2.5,-3 2.5,1 ; 1,-3.25 3,-3.25 3,1 ; 2.5,1 2.5,1.75 ; 2.5,1 3,1 ; 2.5,1.75 3,1.75
  text "1" at -2.25,-2.5 h0.94

## 87832-06 [mm]
pads (8):
  rect 1x2.75 smd: 1(-2,-2.15) 2(-2,2.15) 3(0,-2.15) 4(0,2.15) 5(2,-2.15) 6(2,2.15)
  round 1 hole 1: 1(-1,0) 1(1,0)
Top Overlay:
  lines w0.203: -4.4,-3.75 4.4,-3.75 4.4,3.75 -4.4,3.75 -4.4,-3.75
Mechanical 16:
  rectangle: -2.5,0.5 -1.5,1.5
  rectangle: -0.5,0.5 0.5,1.5
  rectangle: 1.5,0.5 2.5,1.5
  rectangle: -2.5,-1.5 -1.5,-0.5
  rectangle: -0.5,-1.5 0.5,-0.5
  rectangle: 1.5,-1.5 2.5,-0.5
  lines w0.051: -4.25,-1.75 -4,-1.75 ; -4.25,-0.75 -4,-0.75 ; -1,-3.75 -1,-3.25 ; 1,-3.75 1,-3.25 ; 4.25,1 4,1 ; 4.25,1.75 4,1.75 ; -4,-1.75 -3.5,-1.75 ; -4,-1.75 -4,-3.25 -1,-3.25 ; -4,-0.75 -3.5,-0.75 ; -4,-0.75 -4,3.25 4,3.25 4,1.75 ; -3.5,-1.75 -3.5,-0.75 ; -3.5,-1.75 -3.5,-3 -2.25,-3 -2.25,-2.75 -1.75,-2.75 -1.75,-3 -1,-3 -1,-3.25 ; -3.5,-0.75 -3.5,3 -2.25,3 -2.25,2.75 -1.75,2.75 -1.75,3 -0.25,3 -0.25,2.75 0.25,2.75 0.25,3 1.75,3 1.75,2.75 2.25,2.75 2.25,3 3.5,3 3.5,1.75 ; 1,-3.25 1,-3 1.75,-3 1.75,-2.75 2.25,-2.75 2.25,-3 3.5,-3 3.5,1 ; 1,-3.25 4,-3.25 4,1 ; 3.5,1 3.5,1.75 ; 3.5,1 4,1 ; 3.5,1.75 4,1.75
  text "1" at -3.25,-2.75 h0.94

## 87832-08 [mm]
pads (10):
  rect 1x2.75 smd: 1(-3,-2.15) 2(-3,2.15) 3(-1,-2.15) 4(-1,2.15) 5(1,-2.15) 6(1,2.15) 7(3,-2.15) 8(3,2.15)
  round 1 hole 1: 1(-2,0) 1(2,0)
Top Overlay:
  lines w0.203: -5.4,-3.75 5.4,-3.75 5.4,3.75 -5.4,3.75 -5.4,-3.75
Mechanical 16:
  rectangle: -3.5,0.5 -2.5,1.5
  rectangle: -1.5,0.5 -0.5,1.5
  rectangle: 0.5,0.5 1.5,1.5
  rectangle: 2.5,0.5 3.5,1.5
  rectangle: -3.5,-1.5 -2.5,-0.5
  rectangle: -1.5,-1.5 -0.5,-0.5
  rectangle: 0.5,-1.5 1.5,-0.5
  rectangle: 2.5,-1.5 3.5,-0.5
  lines w0.051: -5.25,-1.75 -5,-1.75 ; -5.25,-0.75 -5,-0.75 ; -1,-3.75 -1,-3.25 ; 1,-3.75 1,-3.25 ; 5.25,1 5,1 ; 5.25,1.75 5,1.75 ; -5,-1.75 -4.5,-1.75 ; -5,-1.75 -5,-3.25 -1,-3.25 ; -5,-0.75 -4.5,-0.75 ; -5,-0.75 -5,3.25 5,3.25 5,1.75 ; -4.5,-1.75 -4.5,-0.75 ; -4.5,-1.75 -4.5,-3 -3.25,-3 -3.25,-2.75 -2.75,-2.75 -2.75,-3 -1,-3 -1,-3.25 ; -4.5,-0.75 -4.5,3 -3.25,3 -3.25,2.75 -2.75,2.75 -2.75,3 -1.25,3 -1.25,2.75 -0.75,2.75 -0.75,3 0.75,3 0.75,2.75 1.25,2.75 1.25,3 2.75,3 2.75,2.75 3.25,2.75 3.25,3 4.5,3 4.5,1.75 ; 1,-3.25 1,-3 2.75,-3 2.75,-2.75 3.25,-2.75 3.25,-3 4.5,-3 4.5,1 ; 1,-3.25 5,-3.25 5,1 ; 4.5,1 4.5,1.75 ; 4.5,1 5,1 ; 4.5,1.75 5,1.75
  text "1" at -4.25,-2.75 h0.94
